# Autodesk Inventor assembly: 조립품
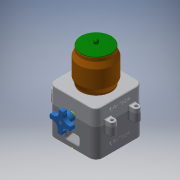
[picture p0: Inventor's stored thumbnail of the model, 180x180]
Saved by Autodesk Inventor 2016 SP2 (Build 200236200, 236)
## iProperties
Created: 2018-01
Part Number: 조립품
Document SubType Name: Assembly
Designer: Administrator
Author: Administrator
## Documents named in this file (9)
- D:\480107V1007\조립품.iam
- D:\480107V1007\본체.ipt
- D:\480107V1007\핸들축.ipt
- D:\480107V1007\핸들.ipt
- D:\480107V1007\볼트 M3x12.ipt
- D:\480107V1007\용기.ipt
- D:\480107V1007\본체커버.ipt
- D:\480107V1007\볼트 M4x12.ipt
- D:\480107V1007\용기캡.ipt
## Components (2 placed, 2 different names)
1. 핸들축:1
2. 핸들:1
